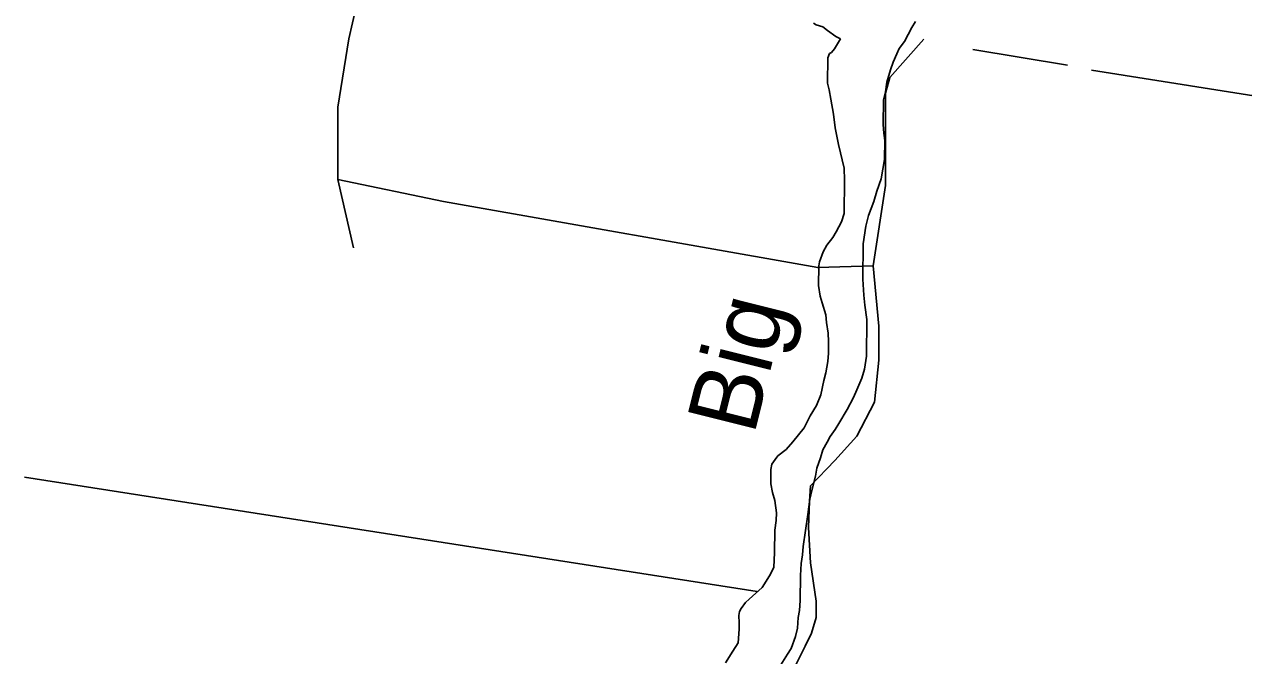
# Model space of a CAD drawing. Extents: x 3161514 to 3199414, y 831166 to 856601.
# Drawn here: x 3166350 to 3168099, y 843882 to 844788 of the extents above; entities that cross this region are included whole.
import ezdxf

# ---------------------------------------------------------------- set-up
doc = ezdxf.new("R2010")
doc.units = 0
for name, color, linetype in [('V-RIVR-IDEN', 7, 'Continuous'), ('V-SITE-VEGE', 7, 'Continuous'), ('V-TOPO-SHOR', 7, 'Continuous')]:
    doc.layers.add(name, color=color, linetype=linetype)

msp = doc.modelspace()

# ---------------------------------------------------------------- linework, layer by layer
at = {"layer": 'V-SITE-VEGE'}
for p, q in [((3167486.2, 844787.2), (3167482, 844789.8)), ((3167495.6, 844784.5), (3167486.2, 844787.2)), ((3167502.3, 844779.3), (3167495.6, 844784.5)), ((3167623.4, 844783.6), (3167612.9, 844763.3)), ((3167628.6, 844792.1), (3167623.4, 844783.6)), ((3167514.1, 844770.6), (3167502.3, 844779.3)), ((3167512.2, 844752.8), (3167520.9, 844767.1)), ((3167520.9, 844767.1), (3167514.1, 844770.6)), ((3167507.9, 844747.7), (3167512.2, 844752.8)), ((3167605.1, 844753.2), (3167601.6, 844745.6)), ((3167612.9, 844763.3), (3167605.1, 844753.2)), ((3167502.1, 844703.5), (3167502.6, 844740.1)), ((3167502.6, 844740.1), (3167505.3, 844746)), ((3167505.3, 844746), (3167507.9, 844747.7)), ((3167596.3, 844733.7), (3167592.7, 844722.7)), ((3167601.6, 844745.6), (3167596.3, 844733.7)), ((3167592.7, 844722.7), (3167587.4, 844704.9)), ((3167504.6, 844694.1), (3167502.1, 844703.5)), ((3167587.4, 844704.9), (3167585.5, 844691.3)), ((3167506.9, 844680.4), (3167504.6, 844694.1)), ((3167510.9, 844659.1), (3167506.9, 844680.4)), ((3167582.7, 844679.4), (3167582.3, 844644.4)), ((3167585.5, 844691.3), (3167582.7, 844679.4)), ((3167513.2, 844639.4), (3167510.9, 844659.1)), ((3167582.3, 844644.4), (3167582.9, 844631.6)), ((3167518, 844615.5), (3167513.2, 844639.4)), ((3167582.9, 844631.6), (3167584.5, 844621.4)), ((3167526, 844581.3), (3167518, 844615.5)), ((3167584.5, 844621.4), (3167584.1, 844594.1)), ((3167584.1, 844594.1), (3167579.5, 844566.1)), ((3167526.6, 844564.3), (3167526, 844581.3)), ((3167526, 844516.5), (3167526.6, 844564.3)), ((3167579.5, 844566.1), (3167573.3, 844548.3)), ((3167573.3, 844548.3), (3167568.8, 844533.8)), ((3167568.8, 844533.8), (3167560.9, 844513.5)), ((3167514.5, 844490.3), (3167522.4, 844504.7)), ((3167522.4, 844504.7), (3167526, 844516.5)), ((3167560.9, 844513.5), (3167557.2, 844498.2)), ((3167510.1, 844481.8), (3167514.5, 844490.3)), ((3167557.2, 844498.2), (3167553.5, 844472.7)), ((3167496.2, 844461.6), (3167501.5, 844470.9)), ((3167501.5, 844470.9), (3167510.1, 844481.8)), ((3167553.5, 844472.7), (3167552.8, 844422.4)), ((3167490.9, 844447.2), (3167496.2, 844461.6)), ((3167489.6, 844413.1), (3167490, 844441.2)), ((3167490, 844441.2), (3167490.9, 844447.2)), ((3167552.8, 844422.4), (3167554.2, 844399.4)), ((3167491.9, 844397.7), (3167489.6, 844413.1)), ((3167554.2, 844399.4), (3167555.7, 844384.9)), ((3167494.4, 844388.3), (3167491.9, 844397.7)), ((3167500.1, 844371.2), (3167494.4, 844388.3)), ((3167555.7, 844384.9), (3167558.8, 844364.4)), ((3167500.8, 844360.1), (3167500.1, 844371.2)), ((3167558.8, 844364.4), (3167558.1, 844311.6)), ((3167503.1, 844344.7), (3167500.8, 844360.1)), ((3167503.8, 844332.8), (3167503.1, 844344.7)), ((3167503.6, 844315.8), (3167503.8, 844332.8)), ((3167502.6, 844303.8), (3167503.6, 844315.8)), ((3167558.1, 844311.6), (3167555.3, 844292.9)), ((3167499.8, 844287.7), (3167502.6, 844303.8)), ((3167555.3, 844292.9), (3167551.7, 844280.2)), ((3167492.6, 844256.3), (3167497.1, 844276.6)), ((3167497.1, 844276.6), (3167499.8, 844287.7)), ((3167551.7, 844280.2), (3167544.6, 844263.2)), ((3167544.6, 844263.2), (3167539.4, 844252.2)), ((3167477.6, 844225.8), (3167486.4, 844241)), ((3167486.4, 844241), (3167492.6, 844256.3)), ((3167539.4, 844252.2), (3167530.6, 844235.3)), ((3167468.9, 844208.9), (3167477.6, 844225.8)), ((3167530.6, 844235.3), (3167518.4, 844215)), ((3167452.4, 844188.6), (3167468.9, 844208.9)), ((3167513.2, 844206.6), (3167506.2, 844196.4)), ((3167518.4, 844215), (3167513.2, 844206.6)), ((3167442.9, 844177.7), (3167452.4, 844188.6)), ((3167501.8, 844188), (3167495.7, 844177)), ((3167506.2, 844196.4), (3167501.8, 844188)), ((3167430.8, 844168.5), (3167442.9, 844177.7)), ((3167495.7, 844177), (3167492.2, 844165.9)), ((3167421.2, 844149), (3167422.2, 844156.7)), ((3167422.2, 844156.7), (3167427.4, 844163.4)), ((3167427.4, 844163.4), (3167430.8, 844168.5)), ((3167492.2, 844165.9), (3167486.8, 844150.7)), ((3167420.9, 844128.6), (3167421.2, 844149)), ((3167485, 844139.6), (3167480.5, 844120.9)), ((3167486.8, 844150.7), (3167485, 844139.6)), ((3167423.3, 844115.8), (3167420.9, 844128.6)), ((3167480.5, 844120.9), (3167476.9, 844106.5)), ((3167426.6, 844104.6), (3167423.3, 844115.8)), ((3167428.9, 844086.7), (3167426.6, 844104.6)), ((3167476.9, 844106.5), (3167474, 844084.4)), ((3167428.7, 844075.6), (3167428.9, 844086.7)), ((3167474, 844084.4), (3167467.4, 844038.5)), ((3167426.8, 844062), (3167428.7, 844075.6)), ((3167426.4, 844029.7), (3167426.8, 844062)), ((3167467.4, 844038.5), (3167466.4, 844026.6)), ((3167425.2, 844008.4), (3167426.4, 844029.7)), ((3167464.5, 844013.8), (3167463.4, 843996.8)), ((3167466.4, 844026.6), (3167464.5, 844013.8)), ((3167408.6, 843979.6), (3167419.1, 843996.5)), ((3167419.1, 843996.5), (3167425.2, 844008.4)), ((3167463.4, 843996.8), (3167462.9, 843961)), ((3167389.7, 843962.8), (3167408.6, 843979.6)), ((3167384.5, 843957.8), (3167389.7, 843962.8)), ((3167462.9, 843961), (3167461.9, 843946.5)), ((3167374.9, 843939.2), (3167375.8, 843945.1)), ((3167375.8, 843945.1), (3167378.4, 843949.4)), ((3167378.4, 843949.4), (3167384.5, 843957.8)), ((3167461.9, 843946.5), (3167460, 843936.3)), ((3167375.6, 843929), (3167374.9, 843939.2)), ((3167375.4, 843919.6), (3167375.6, 843929)), ((3167460, 843936.3), (3167459, 843921)), ((3167374.3, 843900), (3167375.4, 843919.6)), ((3167456.2, 843909.1), (3167450, 843892.1)), ((3167459, 843921), (3167456.2, 843909.1)), ((3167366.5, 843888.2), (3167374.3, 843900)), ((3167450, 843892.1), (3167444.8, 843883.7)), ((3167356, 843871.3), (3167366.5, 843888.2)), ((3167444.8, 843883.7), (3167435.2, 843868.5))]:
    msp.add_line(p, q, dxfattribs=at)
at = {"layer": 'V-TOPO-SHOR'}
for p, q in [((3167710.8, 844751.7), (3167846.5, 844729.5)), ((3166799.8, 844565.1), (3166821.9, 844467.2)), ((3166349.8, 844138), (3167401.4, 843973.8))]:
    msp.add_line(p, q, dxfattribs=at)
for points in [[(3167568, 844441.5), (3167488.2, 844438.8), (3166951.4, 844533.5), (3166799.8, 844565.1), (3166799.8, 844669.3), (3166815.6, 844767.2), (3166831.4, 844836.7), (3166847.2, 844877.7)], [(3167640.6, 844766.8), (3167591.7, 844711.5), (3167585.3, 844689.4), (3167585.3, 844556.8), (3167568, 844441.5), (3167575.9, 844354.7), (3167575.9, 844305.7), (3167569.5, 844245.7), (3167544.3, 844196.8), (3167512.7, 844162.1), (3167478, 844125.7), (3167476.4, 844103.6), (3167474.8, 844065.7), (3167478, 844015.2), (3167485.9, 843960), (3167485.9, 843936.3), (3167479.5, 843914.2), (3167470.1, 843895.2), (3167449.5, 843854.2)], [(3167881, 844722.1), (3168537.2, 844618.5), (3169575.7, 844453.2), (3170841.1, 844255.9), (3170804.1, 843935.2), (3170747.4, 843473.9), (3170661, 842788.2), (3170614.2, 842450.2)]]:
    msp.add_lwpolyline(points, dxfattribs=at)

# ---------------------------------------------------------------- texts
at = {"layer": 'V-RIVR-IDEN'}
msp.add_text('Big', height=100, rotation=75.9638, dxfattribs=at).set_placement((3167396.7, 844196.6))

doc.saveas('drawing.dxf')
